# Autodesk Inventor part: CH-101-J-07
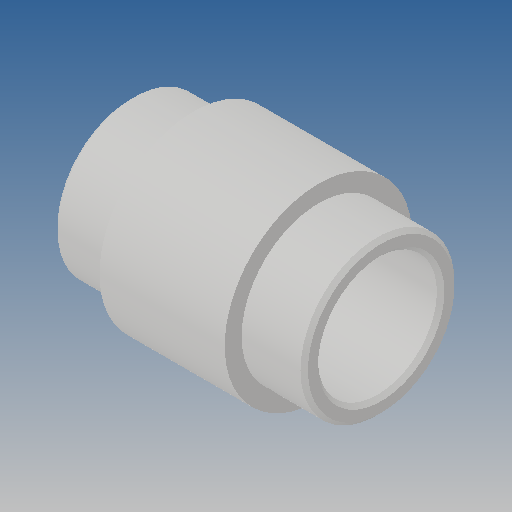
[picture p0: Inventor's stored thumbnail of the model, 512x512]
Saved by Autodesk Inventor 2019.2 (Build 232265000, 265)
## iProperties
Created: 2012-09
Part Number: CH-101-J-07
Material: Ogólny
Document SubType Name: Modeling
Designer: CADENGINEERING4
Density: 1 g/cm^3
Appearance: Domyślna
Author: CADENGINEERING4
Revision Number: ÈÎºÎ
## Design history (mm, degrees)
feature "µ¹½Ç1"
node "Bryła1"
